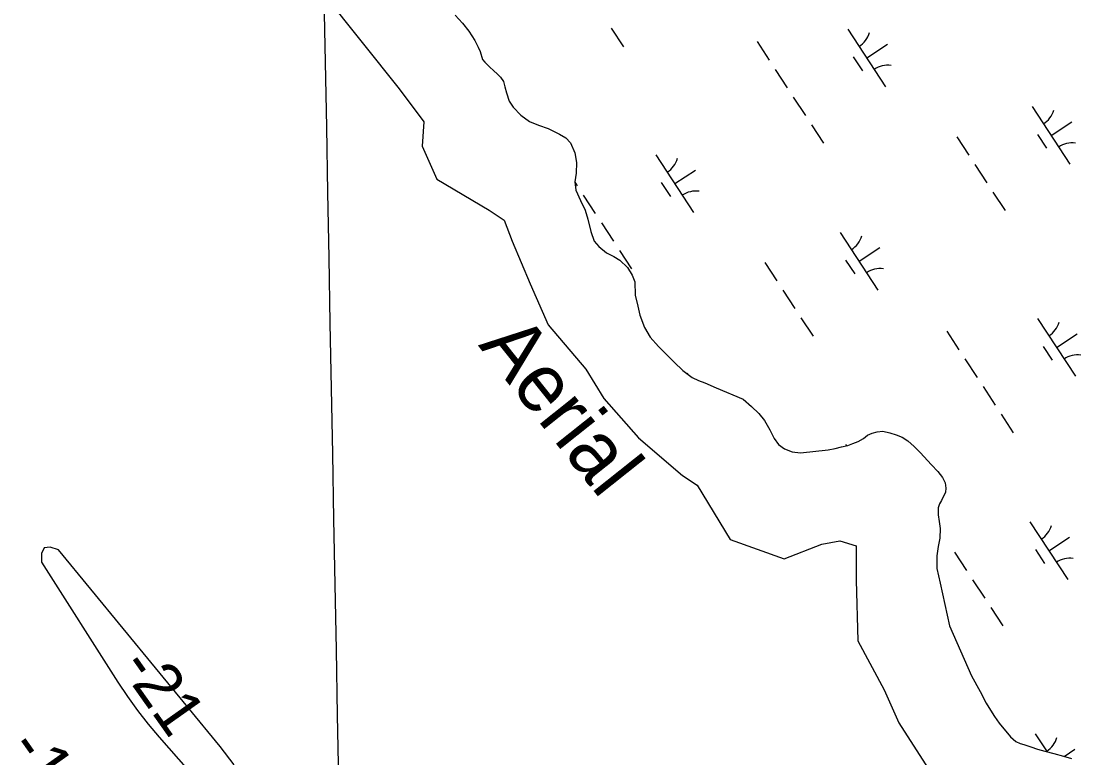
# Model space of a CAD drawing. Extents: x 3945642 to 3966284, y 206476 to 228921.
# Drawn here: x 3956738 to 3957506, y 217128 to 217662 of the extents above; entities that cross this region are included whole.
import ezdxf

# ---------------------------------------------------------------- set-up
doc = ezdxf.new("R2010")
doc.units = 0
for name, color, linetype in [('V-GRID-MAJR', 7, 'Continuous'), ('V-RIVR-EDGE', 7, 'Continuous'), ('V-RIVR-IDEN', 7, 'Continuous'), ('V-RIVR-RANG', 7, 'Continuous'), ('V-TOPO-DPTH', 7, 'Continuous'), ('V-TOPO-MINR', 7, 'Continuous'), ('V-WETL-SWMP', 7, 'Continuous')]:
    doc.layers.add(name, color=color, linetype=linetype)

msp = doc.modelspace()

# ---------------------------------------------------------------- linework, layer by layer
at = {"layer": 'V-GRID-MAJR'}
msp.add_spline([(3957114.32, 209221.5), (3957056.9, 212329.82), (3956944.95, 218389.75), (3956833, 224449.67), (3956787.83, 226894.45)], degree=3, dxfattribs=at)
at = {"layer": 'V-RIVR-EDGE'}
msp.add_lwpolyline([(3956957.73, 217681.55), (3957012.34, 217612.69), (3957030.15, 217588.94), (3957028.97, 217571.13), (3957039.65, 217547.39), (3957077.64, 217524.83), (3957088.33, 217517.71), (3957094.26, 217502.28), (3957107.32, 217471.41), (3957120.38, 217441.73), (3957147.69, 217409.67), (3957160.75, 217388.3), (3957185.68, 217359.81), (3957217.73, 217332.5), (3957228.42, 217325.38), (3957252.16, 217286.2), (3957291.34, 217271.96), (3957318.65, 217282.64), (3957331.71, 217285.02), (3957343.58, 217281.45), (3957343.58, 217256.52), (3957344.76, 217212.6), (3957363.76, 217176.98), (3957374.44, 217153.24), (3957395.81, 217119.99)], dxfattribs=at)
at = {"layer": 'V-TOPO-DPTH'}
for points in [[(3956754.96, 217280.04), (3956753.12, 217276.03), (3956752.99, 217269.67), (3956808.53, 217182.55), (3956815.47, 217172.19), (3956822.72, 217162.06), (3956830.42, 217152.28), (3956838.43, 217142.73), (3956882.07, 217093.07)], [(3956892.64, 217122.81), (3956882.63, 217135.91), (3956765.43, 217278.69), (3956759.34, 217280.54), (3956754.96, 217280.04)]]:
    msp.add_lwpolyline(points, dxfattribs=at)
at = {"layer": 'V-TOPO-MINR'}
for points in [[(3956754.96, 217280.04), (3956753.12, 217276.03), (3956752.99, 217269.67), (3956808.53, 217182.55), (3956815.47, 217172.19), (3956822.72, 217162.06), (3956830.42, 217152.28), (3956838.43, 217142.73), (3956882.07, 217093.07)], [(3956892.64, 217122.81), (3956882.63, 217135.91), (3956765.43, 217278.69), (3956759.34, 217280.54), (3956754.96, 217280.04)]]:
    msp.add_lwpolyline(points, dxfattribs=at)
at = {"layer": 'V-WETL-SWMP'}
for p, q in [((3957052.94, 217666.13), (3957058.23, 217660.33)), ((3957058.23, 217660.33), (3957062.73, 217654.6)), ((3957062.73, 217654.6), (3957067.15, 217647.87)), ((3957166.05, 217656.69), (3957174.82, 217643.3)), ((3957337.51, 217656.13), (3957364.91, 217614.31)), ((3957067.15, 217647.87), (3957069.56, 217642.95)), ((3957271.72, 217647.01), (3957280.49, 217633.62)), ((3957351.21, 217635.22), (3957366.27, 217645.08)), ((3957069.56, 217642.95), (3957070.98, 217639.92)), ((3957070.98, 217639.92), (3957072.67, 217634.07)), ((3957341.47, 217636.01), (3957348.05, 217625.97)), ((3957072.67, 217634.07), (3957074.31, 217632.25)), ((3957074.31, 217632.25), (3957077.75, 217628.7)), ((3957077.75, 217628.7), (3957080.9, 217625.94)), ((3957080.9, 217625.94), (3957083.48, 217623.68)), ((3957083.48, 217623.68), (3957085.77, 217621.36)), ((3957085.77, 217621.36), (3957087.98, 217618.03)), ((3957284.87, 217626.93), (3957293.64, 217613.55)), ((3957087.98, 217618.03), (3957088.96, 217614.35)), ((3957088.96, 217614.35), (3957090.08, 217609.87)), ((3957090.08, 217609.87), (3957092.13, 217603.95)), ((3957298.02, 217606.86), (3957306.79, 217593.47)), ((3957092.13, 217603.95), (3957094.98, 217599.53)), ((3957094.98, 217599.53), (3957100.41, 217593.8)), ((3957471.1, 217599.91), (3957498.5, 217558.08)), ((3957100.41, 217593.8), (3957106.72, 217589.22)), ((3957106.72, 217589.22), (3957113.33, 217586.36)), ((3957113.33, 217586.36), (3957120.31, 217584.08)), ((3957120.31, 217584.08), (3957128.49, 217579.84)), ((3957311.17, 217586.78), (3957319.94, 217573.4)), ((3957484.8, 217578.99), (3957499.85, 217588.86)), ((3957128.49, 217579.84), (3957133.08, 217577.28)), ((3957133.08, 217577.28), (3957136.45, 217573.66)), ((3957416.41, 217578.07), (3957425.17, 217564.69)), ((3957475.06, 217579.79), (3957481.63, 217569.75)), ((3957136.45, 217573.66), (3957139.64, 217566.36)), ((3957139.64, 217566.36), (3957140.81, 217559.5)), ((3957140.81, 217559.5), (3957140.61, 217551.79)), ((3957198.37, 217564.98), (3957225.77, 217523.16)), ((3957140.61, 217551.79), (3957139.63, 217545.31)), ((3957212.07, 217544.07), (3957227.13, 217553.93)), ((3957429.56, 217557.99), (3957438.32, 217544.61)), ((3957139.63, 217545.31), (3957140.45, 217539.4)), ((3957139.67, 217545.03), (3957141.35, 217542.47)), ((3957202.33, 217544.86), (3957208.91, 217534.82)), ((3957140.45, 217539.4), (3957143.79, 217531.88)), ((3957442.71, 217537.92), (3957451.48, 217524.53)), ((3957143.79, 217531.88), (3957147.12, 217524.8)), ((3957145.73, 217535.78), (3957154.5, 217522.4)), ((3957147.12, 217524.8), (3957149.17, 217518.3)), ((3957149.17, 217518.3), (3957151.19, 217509.49)), ((3957158.88, 217515.71), (3957167.65, 217502.32)), ((3957151.19, 217509.49), (3957153.59, 217502.48)), ((3957331.96, 217508.76), (3957359.36, 217466.93)), ((3957153.59, 217502.48), (3957157.02, 217498.49)), ((3957157.02, 217498.49), (3957162.61, 217493.99)), ((3957162.61, 217493.99), (3957167.86, 217491.36)), ((3957167.86, 217491.36), (3957172.23, 217488.51)), ((3957172.03, 217495.63), (3957180.8, 217482.25)), ((3957345.66, 217487.84), (3957360.72, 217497.71)), ((3957172.23, 217488.51), (3957177.89, 217483.21)), ((3957177.89, 217483.21), (3957181.31, 217477.78)), ((3957277.27, 217486.92), (3957286.03, 217473.53)), ((3957335.92, 217488.63), (3957342.49, 217478.6)), ((3957181.31, 217477.78), (3957183.07, 217472.94)), ((3957183.07, 217472.94), (3957183.44, 217463.21)), ((3957183.44, 217463.21), (3957185.25, 217455.2)), ((3957290.42, 217466.84), (3957299.19, 217453.46)), ((3957185.25, 217455.2), (3957186.72, 217448.78)), ((3957186.72, 217448.78), (3957190.19, 217439.67)), ((3957303.57, 217446.77), (3957312.34, 217433.38)), ((3957475.03, 217446.21), (3957502.43, 217404.39)), ((3957190.19, 217439.67), (3957194.32, 217432.87)), ((3957409.24, 217437.09), (3957418.01, 217423.71)), ((3957194.32, 217432.87), (3957200.25, 217426.05)), ((3957488.73, 217425.3), (3957503.79, 217435.17)), ((3957200.25, 217426.05), (3957206.12, 217420.1)), ((3957478.99, 217426.09), (3957485.57, 217416.05)), ((3957206.12, 217420.1), (3957211.63, 217414.59)), ((3957211.63, 217414.59), (3957217.85, 217408.56)), ((3957422.39, 217417.01), (3957431.16, 217403.63)), ((3957217.85, 217408.56), (3957224.59, 217403.61)), ((3957221.05, 217406.21), (3957221.58, 217406.56)), ((3957224.59, 217403.61), (3957229.4, 217401.27)), ((3957229.4, 217401.27), (3957233.93, 217399.65)), ((3957233.93, 217399.65), (3957242.05, 217396.14)), ((3957242.05, 217396.14), (3957261.74, 217387.71)), ((3957435.54, 217396.94), (3957444.31, 217383.55)), ((3957261.74, 217387.71), (3957267.68, 217382.62)), ((3957267.68, 217382.62), (3957272.98, 217377.4)), ((3957272.98, 217377.4), (3957277.05, 217372.25)), ((3957448.69, 217376.86), (3957457.46, 217363.48)), ((3957277.05, 217372.25), (3957281.03, 217365.52)), ((3957281.03, 217365.52), (3957284.23, 217359.23)), ((3957348.95, 217359.27), (3957351.84, 217361.63)), ((3957351.84, 217361.63), (3957355.17, 217363.27)), ((3957355.17, 217363.27), (3957358.85, 217364.25)), ((3957358.85, 217364.25), (3957362.82, 217364.51)), ((3957362.82, 217364.51), (3957367.85, 217363.46)), ((3957367.85, 217363.46), (3957372.53, 217362.06)), ((3957372.53, 217362.06), (3957376.84, 217360.16)), ((3957376.84, 217360.16), (3957381, 217357.53)), ((3957284.23, 217359.23), (3957287.37, 217354.96)), ((3957287.37, 217354.96), (3957291.67, 217351.83)), ((3957323.23, 217351.03), (3957328.28, 217352.07)), ((3957328.28, 217352.07), (3957333.05, 217353.19)), ((3957333.05, 217353.19), (3957337.52, 217354.31)), ((3957335.89, 217355.06), (3957336.55, 217354.07)), ((3957337.52, 217354.31), (3957341.21, 217355.58)), ((3957341.21, 217355.58), (3957345.11, 217357.07)), ((3957345.11, 217357.07), (3957348.95, 217359.27)), ((3957381, 217357.53), (3957385.58, 217353.39)), ((3957385.58, 217353.39), (3957389.88, 217349.11)), ((3957291.67, 217351.83), (3957297.14, 217349.7)), ((3957297.14, 217349.7), (3957303.11, 217349.01)), ((3957303.11, 217349.01), (3957323.23, 217351.03)), ((3957389.88, 217349.11), (3957398.1, 217340.33)), ((3957398.1, 217340.33), (3957402.68, 217335.33)), ((3957402.68, 217335.33), (3957406.11, 217331.12)), ((3957406.11, 217331.12), (3957408.1, 217327.15)), ((3957408.1, 217327.15), (3957408.65, 217323.4)), ((3957408.65, 217323.4), (3957408.26, 217320.44)), ((3957405.48, 217314.48), (3957403.88, 217312.04)), ((3957408.26, 217320.44), (3957405.48, 217314.48)), ((3957402.92, 217308.95), (3957402.89, 217304.05)), ((3957403.88, 217312.04), (3957402.92, 217308.95)), ((3957402.89, 217304.05), (3957403.72, 217299.07)), ((3957403.72, 217299.07), (3957404.47, 217293.95)), ((3957469.48, 217298.84), (3957496.88, 217257.01)), ((3957404.47, 217293.95), (3957404.21, 217287.11)), ((3957404.21, 217287.11), (3957403.08, 217281.13)), ((3957483.18, 217277.92), (3957498.24, 217287.79)), ((3957403.08, 217281.13), (3957402.1, 217274.15)), ((3957414.79, 217277), (3957423.55, 217263.61)), ((3957473.44, 217278.72), (3957480.01, 217268.68)), ((3957402.1, 217274.15), (3957402.11, 217265.14)), ((3957402.11, 217265.14), (3957404.48, 217254.46)), ((3957404.48, 217254.46), (3957411.18, 217223.5)), ((3957427.94, 217256.92), (3957436.71, 217243.54)), ((3957441.09, 217236.85), (3957449.86, 217223.46)), ((3957411.18, 217223.5), (3957427.21, 217187.14)), ((3957427.21, 217187.14), (3957433.32, 217175.92)), ((3957433.32, 217175.92), (3957437.8, 217167.46)), ((3957437.8, 217167.46), (3957440.87, 217162.39)), ((3957440.87, 217162.39), (3957443.79, 217157.76)), ((3957443.79, 217157.76), (3957447.28, 217152.84)), ((3957447.28, 217152.84), (3957450.64, 217148.71)), ((3957450.64, 217148.71), (3957453.14, 217145.66)), ((3957453.14, 217145.66), (3957455.43, 217143.12)), ((3957473.41, 217145.14), (3957481.93, 217132.15)), ((3957455.43, 217143.12), (3957459.29, 217139.56)), ((3957459.29, 217139.56), (3957462.46, 217138.24)), ((3957462.46, 217138.24), (3957465.19, 217137.36)), ((3957465.19, 217137.36), (3957470.08, 217135.88)), ((3957470.08, 217135.88), (3957475.11, 217134.12)), ((3957475.11, 217134.12), (3957480.29, 217132.57)), ((3957480.29, 217132.57), (3957486.91, 217130.86)), ((3957486.91, 217130.86), (3957493.74, 217129.01)), ((3957494.21, 217128.88), (3957502.17, 217134.09)), ((3957493.74, 217129.01), (3957499.71, 217127.39))]:
    msp.add_line(p, q, dxfattribs=at)
for centre, start, end in [((3957336.27, 217658.46), 302.45745, 344.00111), ((3957366.55, 217612.25), 82.45745, 124.00111), ((3957469.86, 217602.23), 302.45745, 344.00111), ((3957500.13, 217556.02), 82.45745, 124.00111), ((3957197.14, 217567.3), 302.45745, 344.00111), ((3957227.41, 217521.09), 82.45745, 124.00111), ((3957330.72, 217511.08), 302.45745, 344.00111), ((3957360.99, 217464.87), 82.45745, 124.00111), ((3957473.79, 217448.54), 302.45745, 344.00111), ((3957504.07, 217402.33), 82.45745, 124.00111), ((3957468.24, 217301.16), 302.45745, 344.00111), ((3957498.51, 217254.95), 82.45745, 124.00111), ((3957472.18, 217147.47), 302.45745, 344.00111)]:
    msp.add_arc(centre, 17.62, start, end, dxfattribs=at)

# ---------------------------------------------------------------- texts
at = {"layer": 'V-RIVR-IDEN'}
msp.add_text('Aerial', height=42, rotation=308.49796, dxfattribs=at).set_placement((3957069.27, 217426.84))
at = {"layer": 'V-RIVR-RANG'}
for s, p in [('-21', (3956809.15, 217193.81)), ('-18', (3956728.22, 217135.06))]:
    msp.add_text(s, height=33.5, rotation=305.27478, dxfattribs=at).set_placement(p)

doc.saveas('drawing.dxf')
